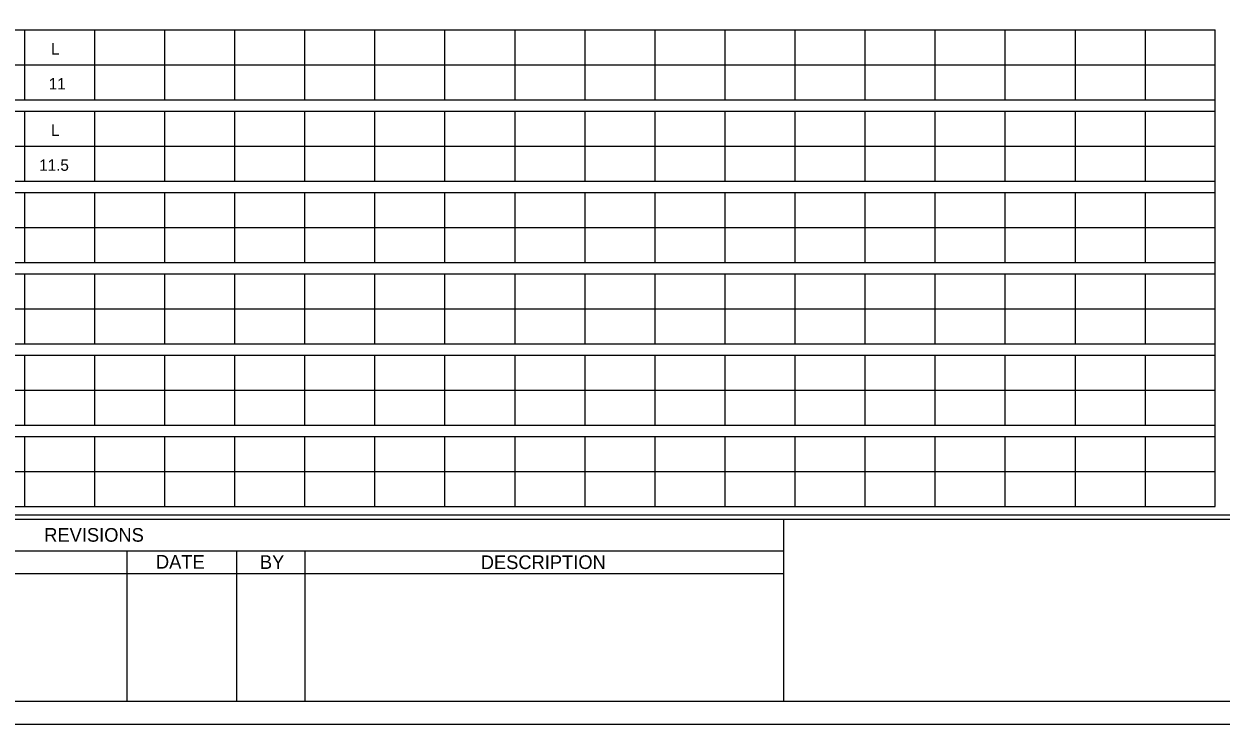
# Model space of a CAD drawing. Extents: x 17890628 to 17890754, y 17897693 to 17897992.
# Drawn here: x 17890694.3 to 17890707.16, y 17897874.81 to 17897882.34 of the extents above; entities that cross this region are included whole.
import ezdxf

# ---------------------------------------------------------------- set-up
doc = ezdxf.new("R2010")
doc.units = 0
for name, color, linetype in [('GSSign', 7, 'Continuous'), ('PlotBorder_dp', 7, 'Continuous'), ('SheetBorder_dp', 7, 'Continuous'), ('SheetLines_dp', 7, 'Continuous'), ('SheetLinesMisc2_dp', 7, 'Continuous'), ('TextMisc', 7, 'Continuous')]:
    doc.layers.add(name, color=color, linetype=linetype)

msp = doc.modelspace()

# ---------------------------------------------------------------- linework, layer by layer
at = {"layer": 'PlotBorder_dp'}
msp.add_lwpolyline([(17890687.002, 17897874.814), (17890727.417, 17897874.814), (17890727.417, 17897900.777), (17890687.002, 17897900.777)], close=True, dxfattribs=at)
at = {"layer": 'SheetBorder_dp'}
for p, q in [((17890688.35, 17897877.018), (17890726.07, 17897877.018)), ((17890688.35, 17897875.059), (17890726.07, 17897875.059))]:
    msp.add_line(p, q, dxfattribs=at)
at = {"layer": 'SheetLines_dp'}
for p, q in [((17890702.458, 17897877.018), (17890702.458, 17897875.059)), ((17890688.35, 17897876.676), (17890702.458, 17897876.676)), ((17890695.404, 17897876.676), (17890695.404, 17897875.059)), ((17890696.58, 17897876.676), (17890696.58, 17897875.059)), ((17890697.314, 17897876.676), (17890697.314, 17897875.059)), ((17890688.35, 17897876.431), (17890702.458, 17897876.431))]:
    msp.add_line(p, q, dxfattribs=at)
at = {"layer": 'SheetLinesMisc2_dp'}
for p, q in [((17890688.597, 17897882.276), (17890707.094, 17897882.276)), ((17890694.303, 17897882.276), (17890694.303, 17897881.524)), ((17890695.055, 17897882.276), (17890695.055, 17897881.524)), ((17890695.807, 17897882.276), (17890695.807, 17897881.524)), ((17890696.56, 17897882.276), (17890696.56, 17897881.524)), ((17890697.312, 17897882.276), (17890697.312, 17897881.524)), ((17890698.065, 17897882.276), (17890698.065, 17897881.524)), ((17890698.817, 17897882.276), (17890698.817, 17897881.524)), ((17890699.57, 17897882.276), (17890699.57, 17897881.524)), ((17890700.322, 17897882.276), (17890700.322, 17897881.524)), ((17890701.074, 17897882.276), (17890701.074, 17897881.524)), ((17890701.827, 17897882.276), (17890701.827, 17897881.524)), ((17890702.579, 17897882.276), (17890702.579, 17897881.524)), ((17890703.332, 17897882.276), (17890703.332, 17897881.524)), ((17890704.084, 17897882.276), (17890704.084, 17897881.524)), ((17890704.836, 17897882.276), (17890704.836, 17897881.524)), ((17890705.589, 17897882.276), (17890705.589, 17897881.524)), ((17890706.341, 17897882.276), (17890706.341, 17897881.524)), ((17890707.094, 17897877.154), (17890707.094, 17897882.276)), ((17890688.597, 17897881.9), (17890707.094, 17897881.9)), ((17890688.597, 17897881.524), (17890707.094, 17897881.524)), ((17890688.597, 17897881.402), (17890707.094, 17897881.402)), ((17890694.303, 17897881.402), (17890694.303, 17897880.65)), ((17890695.055, 17897881.402), (17890695.055, 17897880.65)), ((17890695.807, 17897881.402), (17890695.807, 17897880.65)), ((17890696.56, 17897881.402), (17890696.56, 17897880.65)), ((17890697.312, 17897881.402), (17890697.312, 17897880.65)), ((17890698.065, 17897881.402), (17890698.065, 17897880.65)), ((17890698.817, 17897881.402), (17890698.817, 17897880.65)), ((17890699.57, 17897881.402), (17890699.57, 17897880.65)), ((17890700.322, 17897881.402), (17890700.322, 17897880.65)), ((17890701.074, 17897881.402), (17890701.074, 17897880.65)), ((17890701.827, 17897881.402), (17890701.827, 17897880.65)), ((17890702.579, 17897881.402), (17890702.579, 17897880.65)), ((17890703.332, 17897881.402), (17890703.332, 17897880.65)), ((17890704.084, 17897881.402), (17890704.084, 17897880.65)), ((17890704.836, 17897881.402), (17890704.836, 17897880.65)), ((17890705.589, 17897881.402), (17890705.589, 17897880.65)), ((17890706.341, 17897881.402), (17890706.341, 17897880.65)), ((17890688.597, 17897881.026), (17890707.094, 17897881.026)), ((17890688.597, 17897880.65), (17890707.094, 17897880.65)), ((17890688.597, 17897880.527), (17890707.094, 17897880.527)), ((17890694.303, 17897880.527), (17890694.303, 17897879.776)), ((17890695.055, 17897880.527), (17890695.055, 17897879.776)), ((17890695.807, 17897880.527), (17890695.807, 17897879.776)), ((17890696.56, 17897880.527), (17890696.56, 17897879.776)), ((17890697.312, 17897880.527), (17890697.312, 17897879.776)), ((17890698.065, 17897880.527), (17890698.065, 17897879.776)), ((17890698.817, 17897880.527), (17890698.817, 17897879.776)), ((17890699.57, 17897880.527), (17890699.57, 17897879.776)), ((17890700.322, 17897880.527), (17890700.322, 17897879.776)), ((17890701.074, 17897880.527), (17890701.074, 17897879.776)), ((17890701.827, 17897880.527), (17890701.827, 17897879.776)), ((17890702.579, 17897880.527), (17890702.579, 17897879.776)), ((17890703.332, 17897880.527), (17890703.332, 17897879.776)), ((17890704.084, 17897880.527), (17890704.084, 17897879.776)), ((17890704.836, 17897880.527), (17890704.836, 17897879.776)), ((17890705.589, 17897880.527), (17890705.589, 17897879.776)), ((17890706.341, 17897880.527), (17890706.341, 17897879.776)), ((17890688.597, 17897880.152), (17890707.094, 17897880.152)), ((17890688.597, 17897879.776), (17890707.094, 17897879.776)), ((17890688.597, 17897879.654), (17890707.094, 17897879.654)), ((17890694.303, 17897879.654), (17890694.303, 17897878.902)), ((17890695.055, 17897879.654), (17890695.055, 17897878.902)), ((17890695.807, 17897879.654), (17890695.807, 17897878.902)), ((17890696.56, 17897879.654), (17890696.56, 17897878.902)), ((17890697.312, 17897879.654), (17890697.312, 17897878.902)), ((17890698.065, 17897879.654), (17890698.065, 17897878.902)), ((17890698.817, 17897879.654), (17890698.817, 17897878.902)), ((17890699.57, 17897879.654), (17890699.57, 17897878.902)), ((17890700.322, 17897879.654), (17890700.322, 17897878.902)), ((17890701.074, 17897879.654), (17890701.074, 17897878.902)), ((17890701.827, 17897879.654), (17890701.827, 17897878.902)), ((17890702.579, 17897879.654), (17890702.579, 17897878.902)), ((17890703.332, 17897879.654), (17890703.332, 17897878.902)), ((17890704.084, 17897879.654), (17890704.084, 17897878.902)), ((17890704.836, 17897879.654), (17890704.836, 17897878.902)), ((17890705.589, 17897879.654), (17890705.589, 17897878.902)), ((17890706.341, 17897879.654), (17890706.341, 17897878.902)), ((17890688.597, 17897879.278), (17890707.094, 17897879.278)), ((17890688.597, 17897878.902), (17890707.094, 17897878.902)), ((17890688.597, 17897878.779), (17890707.094, 17897878.779)), ((17890694.303, 17897878.779), (17890694.303, 17897878.028)), ((17890695.055, 17897878.779), (17890695.055, 17897878.028)), ((17890695.807, 17897878.779), (17890695.807, 17897878.028)), ((17890696.56, 17897878.779), (17890696.56, 17897878.028)), ((17890697.312, 17897878.779), (17890697.312, 17897878.028)), ((17890698.065, 17897878.779), (17890698.065, 17897878.028)), ((17890698.817, 17897878.779), (17890698.817, 17897878.028)), ((17890699.57, 17897878.779), (17890699.57, 17897878.028)), ((17890700.322, 17897878.779), (17890700.322, 17897878.028)), ((17890701.074, 17897878.779), (17890701.074, 17897878.028)), ((17890701.827, 17897878.779), (17890701.827, 17897878.028)), ((17890702.579, 17897878.779), (17890702.579, 17897878.028)), ((17890703.332, 17897878.779), (17890703.332, 17897878.028)), ((17890704.084, 17897878.779), (17890704.084, 17897878.028)), ((17890704.836, 17897878.779), (17890704.836, 17897878.028)), ((17890705.589, 17897878.779), (17890705.589, 17897878.028)), ((17890706.341, 17897878.779), (17890706.341, 17897878.028)), ((17890688.597, 17897878.404), (17890707.094, 17897878.404)), ((17890688.597, 17897878.028), (17890707.094, 17897878.028)), ((17890688.597, 17897877.905), (17890707.094, 17897877.905)), ((17890694.303, 17897877.905), (17890694.303, 17897877.154)), ((17890695.055, 17897877.905), (17890695.055, 17897877.154)), ((17890695.807, 17897877.905), (17890695.807, 17897877.154)), ((17890696.56, 17897877.905), (17890696.56, 17897877.154)), ((17890697.312, 17897877.905), (17890697.312, 17897877.154)), ((17890698.065, 17897877.905), (17890698.065, 17897877.154)), ((17890698.817, 17897877.905), (17890698.817, 17897877.154)), ((17890699.57, 17897877.905), (17890699.57, 17897877.154)), ((17890700.322, 17897877.905), (17890700.322, 17897877.154)), ((17890701.074, 17897877.905), (17890701.074, 17897877.154)), ((17890701.827, 17897877.905), (17890701.827, 17897877.154)), ((17890702.579, 17897877.905), (17890702.579, 17897877.154)), ((17890703.332, 17897877.905), (17890703.332, 17897877.154)), ((17890704.084, 17897877.905), (17890704.084, 17897877.154)), ((17890704.836, 17897877.905), (17890704.836, 17897877.154)), ((17890705.589, 17897877.905), (17890705.589, 17897877.154)), ((17890706.341, 17897877.905), (17890706.341, 17897877.154)), ((17890688.597, 17897877.53), (17890707.094, 17897877.53)), ((17890688.597, 17897877.154), (17890707.094, 17897877.154)), ((17890688.417, 17897877.063), (17890726.026, 17897877.063))]:
    msp.add_line(p, q, dxfattribs=at)

# ---------------------------------------------------------------- texts
at = {"layer": 'GSSign'}
for s, height, p in [('L', 0.123, (17890694.589, 17897882.01)), ('11', 0.1225, (17890694.563, 17897881.635)), ('L', 0.123, (17890694.589, 17897881.136)), ('11.5', 0.1225, (17890694.461, 17897880.761))]:
    msp.add_text(s, height=height, dxfattribs=at).set_placement(p)
at = {"layer": 'TextMisc'}
for s, p in [('REVISIONS', (17890694.515, 17897876.774)), ('BY', (17890696.832, 17897876.482))]:
    msp.add_text(s, height=0.147, dxfattribs=at).set_placement(p)
for s, height, rotation, p in [('DATE', 0.147, 359.8693, (17890695.715, 17897876.485)), ('DESCRIPTION', 0.14693, 0.0498, (17890699.205, 17897876.48))]:
    msp.add_text(s, height=height, rotation=rotation, dxfattribs=at).set_placement(p)

doc.saveas('drawing.dxf')
